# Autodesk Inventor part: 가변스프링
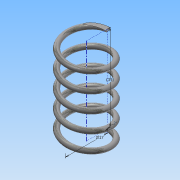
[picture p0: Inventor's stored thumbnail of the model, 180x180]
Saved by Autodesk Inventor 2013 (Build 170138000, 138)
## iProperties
Created: 2017-02
Part Number: 가변스프링
Material: 강철, 탄소
Document SubType Name: Modeling
Designer: Administrator
Mass: 6.52218 g
Surface Area: 16.8021 cm^2
Volume: 0.82874 cm^3
Density: 7.87 g/cm^3
Author: Administrator
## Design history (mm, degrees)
sketch "스케치1"
  geometry: L1 (0, 0)-(8.5, 0); L2 (8.5, 0)-(8.5, 35); L3 (8.5, 35)-(0, 35); L4 (0, 35)-(0, 0); C1 r 1 at (8.5, 0)
  constraints: 8 end point, 2 parallel, 1 centre point, 1 coincident, 1 horizontal, 1 perpendicular
  dimensions: "d0" = 2 diameter of C1; "d2" = 17 diameter of L2 L4; "d3" = 35 distance of L1.end L2.end (derived)
feature "코일1" sketch "스케치1" pitch "d4" = 10; turns "d6" = 5; dims "d5" = 35 (= d3), "d7" = 0, angle "d8" = 90 deg, angle "d9" = 90 deg, "d10" = 0, "d11" = 0
sketch "스케치2"
  geometry: L1 (0, 7.5)-(0, 9.5) reference; 1 further point
  constraints: 1 vertical alignment
extrude "돌출1" cut sketch "스케치2" stored distance "d12" = 10; taper "d13" = 0 deg
node "작업 평면1"
sketch "스케치3"
  geometry: L1 (0, 9.5)-(0, 7.5) reference; 1 further point
  constraints: 1 vertical alignment
extrude "돌출2" cut sketch "스케치3" stored distance "d14" = 10; taper "d15" = 0 deg
node "솔리드1"
node "절단 모서리 투영1"
node "절단 모서리 투영2"
